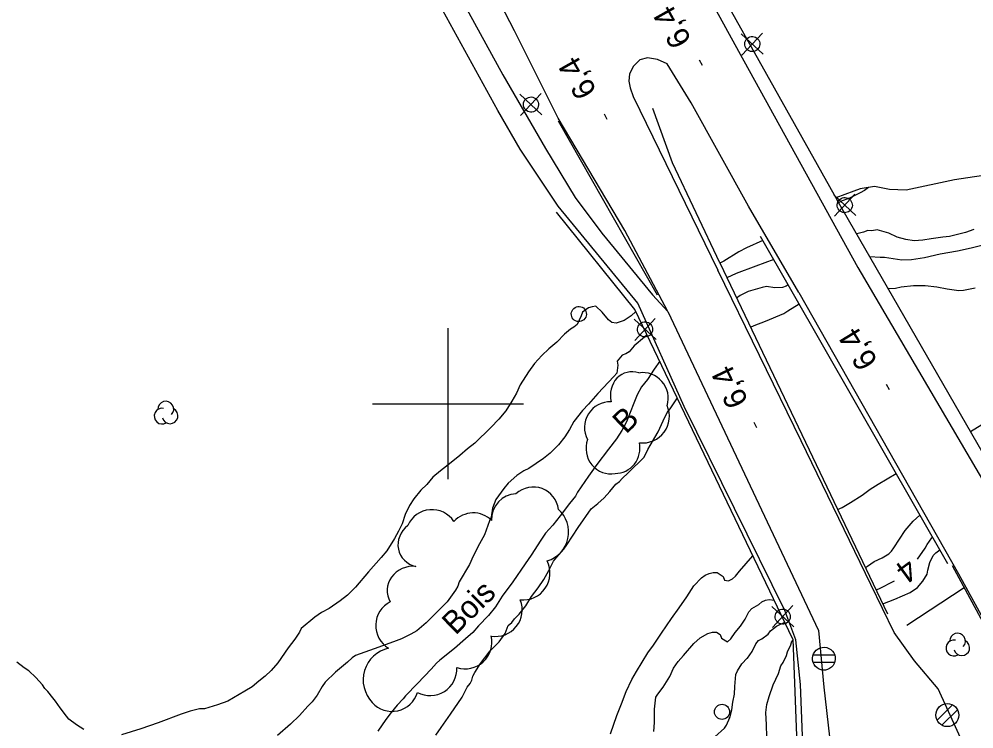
# Model space of a CAD drawing. Extents: x 381879 to 384696, y 5564785 to 5567594.
# Drawn here: x 383743.2 to 383869.7, y 5566356.9 to 5566450.9 of the extents above; entities that cross this region are included whole.
import ezdxf

# ---------------------------------------------------------------- set-up
doc = ezdxf.new("R2010")
doc.units = 0
for name, color, linetype in [('Niveau 2', 7, 'Continuous'), ('Niveau 21', 7, 'Continuous'), ('Niveau 22', 7, 'Continuous'), ('Niveau 26', 7, 'Continuous'), ('Niveau 3', 7, 'Continuous'), ('Niveau 36', 7, 'Continuous'), ('Niveau 4', 7, 'Continuous'), ('Niveau 44', 7, 'Continuous'), ('Niveau 52', 7, 'Continuous'), ('Niveau 61', 7, 'Continuous')]:
    doc.layers.add(name, color=color, linetype=linetype)

msp = doc.modelspace()

# ---------------------------------------------------------------- linework, layer by layer
at = {"layer": 'Niveau 2'}
for points in [[(383855.73, 5566428.64), (383855.19, 5566428.21), (383854.61, 5566427.94), (383853.21, 5566427.21), (383852.01, 5566426.76), (383851.77, 5566426.61)], [(383869.7, 5566423.06), (383868.59, 5566422.68), (383866.45, 5566422.12), (383865.56, 5566422.05), (383864.04, 5566421.83), (383862.94, 5566421.65), (383861.78, 5566421.55), (383860.68, 5566421.72), (383859.51, 5566422.06), (383858.41, 5566422.57), (383856.85, 5566423), (383856.17, 5566422.87), (383855.65, 5566422.91), (383855.06, 5566422.7), (383854.16, 5566422.47)], [(383841.73, 5566421.6), (383839.57, 5566420.65), (383838.54, 5566420.09), (383836.53, 5566418.89), (383836.02, 5566418.61)], [(383871.93, 5566421.27), (383869.33, 5566420.58), (383867.51, 5566420.2), (383865.23, 5566419.79), (383863.12, 5566419.3), (383861.44, 5566419.05), (383860.12, 5566419), (383857.84, 5566419.34), (383857.25, 5566419.34), (383855.91, 5566419.43)], [(383843.17, 5566419.07), (383840.78, 5566418.2), (383838.17, 5566417.25), (383836.95, 5566416.66)], [(383845.09, 5566415.73), (383844.81, 5566415.55), (383844.32, 5566415.39), (383843.29, 5566415.34)], [(383843.29, 5566415.34), (383842.21, 5566415.52), (383841.65, 5566415.4), (383839.79, 5566414.85), (383838.7, 5566414.33), (383838.23, 5566413.99)], [(383824.9, 5566412.21), (383824.29, 5566411.64), (383823.34, 5566411.02), (383822.27, 5566410.65), (383821.7, 5566410.74), (383821.28, 5566411.08), (383820.42, 5566412.11), (383819.61, 5566412.92), (383819.11, 5566412.84), (383818.62, 5566412.67), (383817.82, 5566412.1), (383817.64, 5566411.61), (383817.11, 5566410.5), (383816.69, 5566410.13), (383816.23, 5566409.86), (383815.43, 5566409.21), (383814.43, 5566408.14), (383813.37, 5566407.26), (383812.44, 5566406.37), (383811.48, 5566405.32), (383810.67, 5566404.22), (383809.55, 5566402.49), (383809.06, 5566401.4), (383808.48, 5566400.34), (383807.66, 5566399.04), (383806.73, 5566397.95), (383805.66, 5566396.86)], [(383826.38, 5566409.12), (383826.06, 5566408.82), (383824.68, 5566407.64), (383823.99, 5566406.85), (383823.55, 5566406.59), (383823.07, 5566406.41), (383822.41, 5566405.64), (383822.52, 5566405.1), (383822.39, 5566404.06), (383821.98, 5566403.61)], [(383828.05, 5566405.63), (383827.33, 5566404.59), (383826.42, 5566403.18), (383825.66, 5566402.22), (383825.07, 5566401.15), (383824.62, 5566400.05), (383823.67, 5566397.58), (383823.05, 5566396.46), (383822.35, 5566395.35), (383821.28, 5566393.96), (383819.71, 5566391.95), (383818.64, 5566390.4), (383817.15, 5566388.29), (383816.88, 5566387.74), (383816.11, 5566386.8), (383814.88, 5566385.16), (383813.88, 5566383.93), (383812.93, 5566382.86), (383812.29, 5566381.92), (383811.03, 5566379.95), (383810.22, 5566378.8), (383808.6, 5566376.39), (383807.18, 5566374.53), (383806.3, 5566373.08), (383805.37, 5566371.93), (383804.05, 5566370.6), (383803.27, 5566369.7), (383802.33, 5566368.85), (383800.85, 5566367.57), (383798.9, 5566366.04), (383798.46, 5566365.65), (383797.75, 5566364.86), (383795.96, 5566362.93), (383794.36, 5566361.33), (383794.06, 5566360.92), (383793.27, 5566360.06), (383792.46, 5566359.12), (383791.77, 5566358.19), (383790.72, 5566356.64)], [(383821.98, 5566403.61), (383819.87, 5566401.33), (383818.64, 5566399.92), (383817.81, 5566399.09), (383816.69, 5566397.66), (383816.12, 5566396.56), (383815.48, 5566395.62), (383814.63, 5566394.57), (383813.54, 5566393.45), (383812.67, 5566392.75), (383810.71, 5566391.4), (383810.04, 5566391.09), (383809.13, 5566390.48), (383807.99, 5566389.47), (383807.39, 5566388.78), (383806.35, 5566387.3), (383805.89, 5566386.18), (383805.71, 5566384.96), (383805.51, 5566384.48), (383804.82, 5566382.62), (383804.17, 5566381.44), (383803.33, 5566379.82), (383802.87, 5566378.72)], [(383805.66, 5566396.86), (383803.56, 5566394.75), (383802.6, 5566394.04), (383801.59, 5566393.14), (383800.44, 5566392.21), (383798.99, 5566391.11), (383798, 5566390.26), (383797.18, 5566389.28), (383796.4, 5566388.55), (383795.46, 5566387.4), (383794.89, 5566386.51), (383794.33, 5566385.31), (383793.91, 5566384.11), (383793.45, 5566383.1), (383792.92, 5566382.16), (383791.88, 5566380.52), (383791.14, 5566379.64), (383789.47, 5566377.73), (383787.73, 5566375.71), (383786.7, 5566374.64), (383785.71, 5566373.89), (383784.26, 5566372.87), (383783.26, 5566372.34), (383782.36, 5566371.71), (383780.54, 5566370.22), (383780.31, 5566369.73), (383779.69, 5566368.81), (383778.83, 5566367.66), (383777.45, 5566365.67), (383776.56, 5566364.65), (383775.79, 5566363.92), (383774.94, 5566363.27), (383774.03, 5566362.49), (383773.09, 5566361.91), (383770.84, 5566360.62), (383769.48, 5566360.13), (383767.74, 5566359.58), (383767.09, 5566359.58), (383765.83, 5566359.29), (383764.66, 5566358.87), (383761.6, 5566357.75), (383759.29, 5566356.96), (383756.73, 5566356.17)], [(383855.31, 5566378.29), (383855.57, 5566378.5), (383856.48, 5566379.11), (383857.52, 5566379.59), (383858.42, 5566380.1), (383858.77, 5566380.47), (383859.06, 5566380.91), (383860.58, 5566383.21), (383861.66, 5566384.44), (383862.54, 5566385.25)], [(383862.23, 5566379.43), (383863.25, 5566380.87), (383863.49, 5566381.34), (383864.12, 5566382.22), (383864.22, 5566382.32)], [(383857.61, 5566373.5), (383859.19, 5566374.11), (383861.24, 5566374.99), (383862.21, 5566375.66), (383862.94, 5566376.48), (383863.48, 5566377.43), (383863.57, 5566377.95), (383863.86, 5566378.95), (383864.31, 5566379.88), (383864.65, 5566380.26), (383865.18, 5566380.64)], [(383802.87, 5566378.72), (383801.48, 5566376.42), (383801.29, 5566375.84), (383800.99, 5566375.32), (383799.91, 5566373.78), (383799.01, 5566372.86), (383797.11, 5566371), (383795.87, 5566369.91), (383795.07, 5566369.49), (383793.83, 5566368.85), (383792.76, 5566368.46), (383790.2, 5566367.54), (383787.76, 5566366.64), (383787.31, 5566366.36), (383786.67, 5566365.77), (383785.09, 5566364.43), (383783.72, 5566363.12), (383783.31, 5566362.55), (383782.66, 5566361.42), (383782.02, 5566360.54), (383781.44, 5566359.95), (383780.34, 5566358.72), (383779.11, 5566357.55), (383777.41, 5566356.06)], [(383856.72, 5566375.35), (383857.11, 5566375.46), (383859.16, 5566376.54)], [(383827.27, 5566356.59), (383827.36, 5566357.79), (383827.37, 5566359.53), (383827.54, 5566361.12), (383827.82, 5566361.55), (383828.52, 5566362.45), (383829.4, 5566363.88), (383829.88, 5566364.98), (383830.51, 5566365.88), (383831.21, 5566366.66), (383832.58, 5566368.25), (383833.43, 5566369.01), (383834.45, 5566369.58), (383835.03, 5566369.73), (383835.59, 5566369.73), (383836.05, 5566369.44), (383836.23, 5566368.96), (383837.05, 5566368.47), (383837.46, 5566368.86), (383838.04, 5566369.71), (383838.78, 5566370.54), (383839.38, 5566371.46), (383839.88, 5566372.45), (383840.28, 5566372.86), (383841.17, 5566373.41), (383841.59, 5566373.74), (383842.06, 5566373.99), (383842.56, 5566374.05), (383843.23, 5566373.99)], [(383839.67, 5566366.31), (383840.29, 5566367.19), (383840.8, 5566368.21), (383841.16, 5566368.62), (383841.6, 5566368.88), (383842.44, 5566369.5), (383842.74, 5566369.93), (383843.55, 5566370.54), (383844.62, 5566371.08)], [(383836.68, 5566347.27), (383837.14, 5566348.27), (383837.68, 5566349.25), (383838.37, 5566350.01), (383839.82, 5566351.67), (383840.63, 5566352.37), (383841.53, 5566352.91), (383841.92, 5566353.25), (383842.16, 5566353.76), (383842.2, 5566354.26), (383842.24, 5566355.87), (383842.21, 5566357.47), (383842.13, 5566359.09), (383842.24, 5566360.17), (383842.57, 5566361.23), (383843.11, 5566362.77), (383843.79, 5566364.28), (383844.1, 5566365.27), (383844.4, 5566365.74), (383844.87, 5566366.67), (383844.99, 5566367.16), (383845.45, 5566368.05), (383845.57, 5566368.55), (383845.71, 5566368.68)], [(383751.74, 5566356.84), (383750.76, 5566357.47), (383749.75, 5566358.21), (383749.45, 5566358.63), (383748.61, 5566359.71), (383748, 5566360.61), (383747.62, 5566361.03), (383746.99, 5566361.87), (383746.56, 5566362.3), (383746.27, 5566362.75), (383745.37, 5566363.74), (383744.45, 5566364.64), (383743.86, 5566365.04), (383742.89, 5566365.78)], [(383835.37, 5566355.9), (383836.63, 5566357.01), (383836.89, 5566357.45), (383837.35, 5566358.45), (383837.62, 5566359.44), (383837.76, 5566360.48), (383837.98, 5566361.52), (383838.02, 5566362.54), (383838.14, 5566364.15), (383838.38, 5566364.62), (383838.93, 5566365.54), (383839.63, 5566366.28), (383839.67, 5566366.31)]]:
    msp.add_lwpolyline(points, dxfattribs=at)
at = {"layer": 'Niveau 21'}
for points in [[(383829.15, 5566412.22), (383823.43, 5566422.94), (383814.58, 5566437.79), (383808.81, 5566449.35), (383801.91, 5566462.72), (383792.68, 5566480.88), (383785.24, 5566495.77), (383776.53, 5566512.63)], [(383821.97, 5566476.79), (383838.49, 5566446.66), (383854.29, 5566418.05)], [(383846.47, 5566414.74), (383839.82, 5566426.14), (383832.24, 5566439.83), (383829.05, 5566444.99), (383827.77, 5566445.57), (383826.45, 5566445.81), (383825.42, 5566445.54), (383824.56, 5566444.7), (383824.05, 5566443.68), (383823.97, 5566442.7), (383824.13, 5566441.84), (383824.55, 5566440.69), (383835.75, 5566417.69)], [(383836.01, 5566418.63), (383829.77, 5566431.91), (383827.15, 5566439.09)], [(383814.59, 5566437.45), (383827.72, 5566414.43)], [(383824.78, 5566412.46), (383814.36, 5566425.34)], [(383846.47, 5566414.74), (383867.63, 5566377.47), (383877.55, 5566359.45), (383882.45, 5566349.17), (383888.29, 5566334.58), (383890.9, 5566326.83), (383890.71, 5566323.89), (383889.26, 5566321.91), (383887.06, 5566320.75), (383884.54, 5566320.26), (383882.21, 5566321.35), (383880.16, 5566324.52), (383878.93, 5566328.35), (383873.2, 5566344.16), (383864.95, 5566362.25), (383861.83, 5566365.93), (383859.1, 5566369.68), (383856.02, 5566376.05), (383846.82, 5566395.07), (383835.75, 5566417.69)], [(383854.29, 5566418.05), (383874.42, 5566383.83)], [(383829.15, 5566412.22), (383849.08, 5566369.97), (383849.8, 5566362.44), (383850.56, 5566355.89), (383851.83, 5566352.18), (383859, 5566335.16), (383861.27, 5566329.28), (383862.09, 5566325.16), (383861.81, 5566320.9), (383860.43, 5566315.87), (383857.92, 5566311.34), (383855.66, 5566308.68), (383853.57, 5566306.65)], [(383866.79, 5566378.58), (383876.98, 5566359.81)], [(383860.78, 5566370.69), (383868.39, 5566375.64)], [(383845.71, 5566368.81), (383846.32, 5566352.51)]]:
    msp.add_lwpolyline(points, dxfattribs=at)
at = {"layer": 'Niveau 22'}
for points in [[(383831.31, 5566399.62), (383825.14, 5566413.33), (383814.61, 5566426.14), (383809.55, 5566433.7), (383806.61, 5566438.8), (383799.33, 5566452.08), (383789.74, 5566470.08), (383781.62, 5566484.9), (383775.69, 5566496.81), (383769.39, 5566510.24), (383762.45, 5566524.93), (383753.75, 5566543.5), (383743.82, 5566563.06), (383730.43, 5566590.21)], [(383928.94, 5566574.92), (383906.19, 5566563.73), (383870.28, 5566546.19), (383842.91, 5566532.67), (383809.67, 5566516.34), (383807.9, 5566514.67), (383807.01, 5566513.07), (383806.6, 5566511.33), (383806.46, 5566509.72), (383806.84, 5566507.88), (383807.4, 5566506.15), (383808.97, 5566503.25), (383820.11, 5566483.51), (383835.47, 5566455.64), (383851.58, 5566426.94)], [(383776.53, 5566512.63), (383774.66, 5566511.5), (383773.85, 5566510.57), (383773.39, 5566509.55), (383773.43, 5566508.46), (383773.99, 5566506.9), (383778.12, 5566497.67), (383782.72, 5566488.66), (383790.01, 5566475.18), (383798.25, 5566460.02), (383807.25, 5566443.53), (383812.9, 5566433.79), (383816.83, 5566427.28), (383820.37, 5566422.59), (383827.09, 5566414.42), (383829.15, 5566412.22)], [(383833.6, 5566304.56), (383838.36, 5566308.03), (383840.99, 5566311.84), (383842.55, 5566316.56), (383843.92, 5566323.33), (383845.06, 5566331.77), (383846.04, 5566341.07), (383846.93, 5566350.44), (383846.96, 5566356.02), (383846.72, 5566362.83), (383846.11, 5566368.72), (383844.63, 5566372.61), (383831.31, 5566399.62)]]:
    msp.add_lwpolyline(points, dxfattribs=at)
at = {"layer": 'Niveau 26'}
for points in [[(383876.09, 5566384.46), (383851.58, 5566426.94)], [(383866.23, 5566378.81), (383841.41, 5566422.15)], [(383836.01, 5566418.63), (383858.23, 5566372.19)], [(383845.71, 5566368.81), (383824.78, 5566412.46)]]:
    msp.add_lwpolyline(points, dxfattribs=at)
at = {"layer": 'Niveau 3'}
for p, q in [((383833.71, 5566444.77), (383833.31, 5566445.47)), ((383821.09, 5566437.62), (383820.73, 5566438.34)), ((383858.5, 5566401.85), (383858.11, 5566402.55)), ((383840.91, 5566396.78), (383840.56, 5566397.5))]:
    msp.add_line(p, q, dxfattribs=at)
at = {"layer": 'Niveau 36'}
for p, q in [((383838.85, 5566448.98), (383841.77, 5566446.26)), ((383838.95, 5566446.16), (383841.67, 5566449.08)), ((383809.62, 5566438.15), (383812.34, 5566441.07)), ((383809.52, 5566440.97), (383812.44, 5566438.25)), ((383851.11, 5566427.65), (383854.03, 5566424.93)), ((383851.21, 5566424.83), (383853.93, 5566427.75)), ((383824.65, 5566411.2), (383827.57, 5566408.48)), ((383824.75, 5566408.38), (383827.47, 5566411.3)), ((383842.89, 5566373.16), (383845.81, 5566370.44)), ((383842.99, 5566370.34), (383845.71, 5566373.26)), ((383851.24, 5566366.68), (383848.34, 5566366.7)), ((383848.36, 5566365.78), (383851.26, 5566365.76)), ((383866.85, 5566360.1), (383864.79, 5566358.06)), ((383865.45, 5566357.42), (383867.51, 5566359.46))]:
    msp.add_line(p, q, dxfattribs=at)
for centre, radius in [((383836.31, 5566359.19), 1), ((383866.16, 5566358.76), 1.52)]:
    msp.add_circle(centre, radius, dxfattribs=at)
for centre, major_axis, ratio in [((383840.32, 5566447.62), (0.799, -0.602), 0.999875), ((383810.99, 5566439.61), (0.799, -0.602), 0.999875), ((383852.58, 5566426.29), (0.799, -0.602), 0.999875), ((383817.34, 5566411.87), (0.799, -0.602), 0.999875), ((383826.12, 5566409.84), (0.799, -0.602), 0.999875), ((383844.36, 5566371.8), (0.799, -0.601), 0.999875), ((383849.81, 5566366.23), (-1.21, 0.91), 0.999874)]:
    msp.add_ellipse(centre, major_axis=major_axis, ratio=ratio, dxfattribs=at)
at = {"layer": 'Niveau 4'}
for points in [[(383858.31, 5566415.27), (383859.31, 5566415.31), (383860.05, 5566415.48), (383861.68, 5566415.64), (383863.21, 5566415.63), (383864.78, 5566415.48), (383866.14, 5566415.2), (383867.71, 5566414.97), (383868.3, 5566415.03), (383869.87, 5566415.35)], [(383840.07, 5566410.14), (383840.57, 5566410.37), (383842.07, 5566410.91), (383844.49, 5566411.94), (383845.03, 5566412.31), (383846.52, 5566413.24)], [(383869.24, 5566396.33), (383871.33, 5566397.61), (383872.48, 5566398.07), (383874.3, 5566398.93), (383875.2, 5566399.47), (383876.65, 5566400.24), (383878.55, 5566401.32), (383879.61, 5566401.84), (383880.85, 5566402.29), (383883.48, 5566403.21), (383886.54, 5566404.32), (383888.12, 5566404.75), (383889.27, 5566404.88), (383891.56, 5566405.09), (383893.65, 5566405.26)], [(383829.46, 5566399.3), (383830.39, 5566400.77)], [(383798.4, 5566356.11), (383799.08, 5566357.11), (383800.33, 5566358.88), (383801.89, 5566361.15), (383802.54, 5566362.45), (383802.92, 5566362.93), (383803.16, 5566363.38), (383803.31, 5566363.9), (383803.56, 5566364.4), (383804.3, 5566365.58), (383805.61, 5566367.29), (383806.76, 5566368.46), (383807.57, 5566369.56), (383807.96, 5566370.62), (383808.45, 5566371.01), (383808.81, 5566371.5), (383809.43, 5566372.11), (383810.33, 5566373.21), (383811.07, 5566374.47), (383811.93, 5566375.6), (383812.7, 5566376.71), (383813.38, 5566377.89), (383813.97, 5566379.13), (383814.41, 5566379.67), (383815.37, 5566380.72), (383815.75, 5566381.31), (383817.23, 5566383.61), (383818.95, 5566386.07), (383819.87, 5566386.77), (383820.68, 5566387.53), (383821.43, 5566388.38), (383822.22, 5566389.32), (383822.74, 5566389.7), (383823.1, 5566390.11), (383823.86, 5566390.83), (383825.98, 5566392.9), (383826.5, 5566393.93), (383826.79, 5566394.48), (383827.84, 5566396.28), (383828.52, 5566397.74), (383829.06, 5566398.82), (383829.46, 5566399.3)], [(383851.63, 5566385.98), (383852.21, 5566386.27), (383853.34, 5566386.92), (383854.88, 5566387.9), (383855.95, 5566388.7), (383857.01, 5566389.35), (383859.39, 5566390.75)], [(383821.54, 5566356.28), (383822.38, 5566358.7), (383823.01, 5566360.26), (383823.6, 5566361.87), (383824.36, 5566363.49), (383824.99, 5566364.54), (383826.47, 5566367.01), (383827.22, 5566368.03), (383828.3, 5566369.59), (383829.6, 5566371.55), (383830.65, 5566372.97), (383831.67, 5566374.44), (383832.58, 5566375.88), (383833.57, 5566376.95), (383834.07, 5566377.28), (383834.61, 5566377.51), (383835.14, 5566377.63), (383835.68, 5566377.64), (383836.47, 5566377.12), (383836.64, 5566376.64), (383837.18, 5566376.55), (383837.68, 5566376.8), (383838.11, 5566377.18), (383838.62, 5566377.8), (383840.41, 5566379.87)]]:
    msp.add_lwpolyline(points, dxfattribs=at)
at = {"layer": 'Niveau 44'}
for centre, major_axis, ratio, start_param, end_param in [((383824.54, 5566400.91), (-0.94, 3.2), 0.899417, 5.717538, 7.798698), ((383825.9, 5566400.78), (-1.24, 3.1), 0.980014, 4.019592, 6.082934), ((383762.12, 5566398.35), (0.836, -0.629), 0.999875, 2.023129, 5.909704), ((383762.61, 5566399.27), (0.836, -0.629), 0.999875, 6.162675, 10.101684), ((383763.17, 5566398.39), (0.836, -0.629), 0.999875, 4.036058, 8.005933), ((383821.36, 5566396.93), (-1.76, -2.83), 0.976363, 3.633994, 5.790784), ((383825.83, 5566398.31), (2.82, -2.09), 0.999808, 5.218587, 7.343274), ((383821.53, 5566394.03), (0.65, -3.27), 0.971246, 4.148154, 6.274889), ((383822.19, 5566394.09), (0.66, 3.27), 0.971946, 3.331853, 5.130018), ((383811.23, 5566385.51), (2.06, 2.8), 0.976164, 5.476082, 7.635246), ((383809.14, 5566384.6), (0.47, -3.44), 0.967231, 3.03876, 4.599333), ((383797.85, 5566382.52), (-3.07, -1.64), 0.986501, 3.223983, 5.38153), ((383803.29, 5566382.11), (-2.69, -2.2), 0.976549, 3.23382, 4.856697), ((383811.98, 5566383), (3.92, -0.83), 0.998013, 5.219022, 7.338138), ((383796.8, 5566381.52), (-3.25, -1.21), 0.900225, 5.054543, 7.218557), ((383809.93, 5566377.59), (2.96, -2.03), 0.999954, 5.21582, 7.343389), ((383795.41, 5566375.25), (-3.48, 0.09), 0.923148, 4.639406, 6.796203), ((383806.32, 5566372.7), (2.74, -2.21), 0.99947, 5.218304, 7.343851), ((383793.87, 5566370.64), (-0.95, -3.35), 0.989809, 3.880089, 6.03083), ((383802.29, 5566368.41), (2.38, -2.59), 0.999916, 5.220938, 7.348606), ((383867.52, 5566368.56), (-0.836, 0.629), 0.999875, 3.020126, 6.959135), ((383793.09, 5566363.42), (-4.16, 1.22), 0.994659, 5.218344, 7.334224), ((383867.03, 5566367.64), (-0.836, 0.629), 0.999875, 5.163765, 9.050341), ((383868.08, 5566367.68), (-0.836, 0.629), 0.999875, 0.893509, 4.863384), ((383797.64, 5566364.88), (1.66, -3.13), 0.999307, 5.294675, 7.419117), ((383792.61, 5566362.68), (3.28, 1.16), 0.982052, 3.514266, 5.667344)]:
    msp.add_ellipse(centre, major_axis=major_axis, ratio=ratio, start_param=start_param, end_param=end_param, dxfattribs=at)
at = {"layer": 'Niveau 52'}
msp.add_lwpolyline([(383930.1, 5566450.25), (383931.59, 5566446.35), (383928.59, 5566444.81), (383922.52, 5566441.39), (383918.42, 5566439.32), (383914.4, 5566437.79), (383911, 5566436.83), (383902.95, 5566434.99), (383896.22, 5566434.35), (383884.65, 5566433.22), (383880.27, 5566432.74), (383877.25, 5566431.91), (383872.73, 5566430.46), (383867.11, 5566429.65), (383860.7, 5566428.25), (383858.49, 5566428.36), (383856.51, 5566428.77), (383854.6, 5566428.46), (383853.76, 5566428.15), (383851.4, 5566427.26)], dxfattribs=at)
at = {"layer": 'Niveau 61'}
for points in [[(383800, 5566410), (383800, 5566400), (383800, 5566390)], [(383790, 5566400), (383800, 5566400), (383810, 5566400)]]:
    msp.add_lwpolyline(points, dxfattribs=at)

# ---------------------------------------------------------------- texts
at = {"layer": 'Niveau 2'}
msp.add_text('4', height=3, rotation=216.295, dxfattribs=at).set_placement((383860.82, 5566379.75))
at = {"layer": 'Niveau 3'}
for rotation, p in [(119.2387, (383832.36, 5566448.13)), (119.5659, (383819.8, 5566441.4)), (121.4434, (383857.06, 5566405.61)), (115.3787, (383839.87, 5566400.29))]:
    msp.add_text('6,4', height=3, rotation=rotation, dxfattribs=at).set_placement(p)
at = {"layer": 'Niveau 44'}
for s, p in [('B', (383823.61, 5566395.88)), ('Bois', (383801, 5566369.26))]:
    msp.add_text(s, height=3, rotation=44.7707, dxfattribs=at).set_placement(p)

doc.saveas('drawing.dxf')
